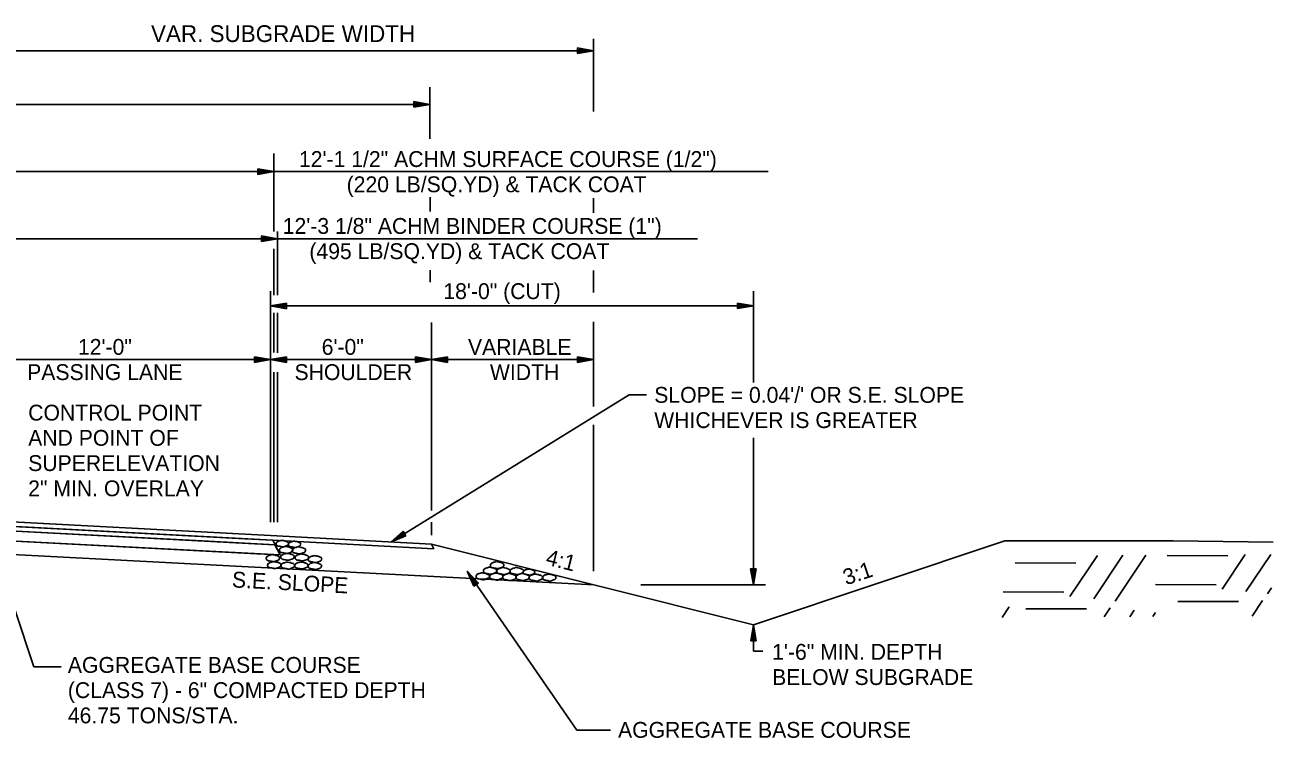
# Model space of a CAD drawing. Extents: x 1398183 to 1398373, y 1967240 to 1968889.
# Drawn here: x 1398257.9 to 1398304.42, y 1968551.85 to 1968578.41 of the extents above; entities that cross this region are included whole.
import ezdxf

# ---------------------------------------------------------------- set-up
doc = ezdxf.new("R2010")
doc.units = 0
for name, color, linetype in [('1', 7, 'Continuous'), ('10', 7, 'Continuous'), ('19', 7, 'Continuous'), ('42', 7, 'Continuous'), ('9', 7, 'Continuous'), ('Default', 7, 'Continuous'), ('Level 1', 7, 'Continuous')]:
    doc.layers.add(name, color=color, linetype=linetype)

# ---------------------------------------------------------------- blocks, each defined once
blk = doc.blocks.new('ROCKS')
at = {"layer": '1'}
blk.add_spline([(0.013, 0.06), (0.053, 0.053), (0.107, 0.033), (0.133, 0.013), (0.133, -0.007), (0.12, -0.033), (0.107, -0.04), (0.073, -0.053), (0.033, -0.067), (0.013, -0.067), (-0.02, -0.06), (-0.06, -0.053), (-0.087, -0.047), (-0.113, -0.02), (-0.113, -0.007), (-0.107, 0.02), (-0.087, 0.033), (-0.067, 0.047), (-0.033, 0.053), (-0.02, 0.06), (0.013, 0.06)], degree=3, dxfattribs=at)

msp = doc.modelspace()

# ---------------------------------------------------------------- linework, layer by layer
at = {"layer": '19'}
for p, q in [((1398279.092, 1968575.187), (1398279.092, 1968577.893)), ((1398255.052, 1968577.446), (1398279.092, 1968577.446)), ((1398278.492, 1968577.551), (1398278.492, 1968577.341)), ((1398279.092, 1968577.446), (1398278.492, 1968577.551)), ((1398278.932, 1968577.461), (1398278.492, 1968577.496)), ((1398278.492, 1968577.341), (1398279.092, 1968577.446)), ((1398278.492, 1968577.391), (1398278.932, 1968577.431)), ((1398272.994, 1968574.171), (1398272.994, 1968576.094)), ((1398272.994, 1968575.446), (1398220.994, 1968575.446)), ((1398272.394, 1968575.551), (1398272.394, 1968575.341)), ((1398272.994, 1968575.446), (1398272.394, 1968575.551)), ((1398272.834, 1968575.461), (1398272.394, 1968575.496)), ((1398272.394, 1968575.341), (1398272.994, 1968575.446)), ((1398272.394, 1968575.391), (1398272.834, 1968575.431)), ((1398267.175, 1968570.713), (1398267.175, 1968573.616)), ((1398255.052, 1968572.946), (1398285.602, 1968572.946)), ((1398266.574, 1968573.051), (1398266.574, 1968572.841)), ((1398267.174, 1968572.946), (1398266.574, 1968573.051)), ((1398267.014, 1968572.961), (1398266.574, 1968572.996)), ((1398266.574, 1968572.841), (1398267.174, 1968572.946)), ((1398266.574, 1968572.891), (1398267.014, 1968572.931)), ((1398273, 1968571.456), (1398273, 1968571.992)), ((1398279.092, 1968571.414), (1398279.092, 1968571.951)), ((1398220.994, 1968570.446), (1398282.96, 1968570.446)), ((1398266.712, 1968570.551), (1398266.712, 1968570.341)), ((1398267.312, 1968570.446), (1398266.712, 1968570.551)), ((1398267.152, 1968570.461), (1398266.712, 1968570.496)), ((1398266.712, 1968570.341), (1398267.312, 1968570.446)), ((1398266.712, 1968570.391), (1398267.152, 1968570.431)), ((1398267.312, 1968568.343), (1398267.312, 1968570.71)), ((1398267.175, 1968568.343), (1398267.175, 1968570.069)), ((1398273, 1968568.833), (1398273, 1968569.274)), ((1398279.092, 1968568.442), (1398279.092, 1968569.257)), ((1398267.052, 1968559.886), (1398267.052, 1968568.492)), ((1398285.051, 1968565.091), (1398285.051, 1968568.492)), ((1398267.652, 1968568.05), (1398267.052, 1968567.946)), ((1398267.652, 1968567.995), (1398267.212, 1968567.961)), ((1398267.652, 1968567.84), (1398267.652, 1968568.05)), ((1398284.452, 1968568.051), (1398284.452, 1968567.841)), ((1398285.052, 1968567.946), (1398284.452, 1968568.051)), ((1398284.892, 1968567.961), (1398284.452, 1968567.996)), ((1398285.052, 1968567.946), (1398267.052, 1968567.946)), ((1398267.052, 1968567.946), (1398267.652, 1968567.84)), ((1398267.175, 1968566.203), (1398267.175, 1968567.691)), ((1398267.212, 1968567.931), (1398267.652, 1968567.89)), ((1398267.312, 1968566.201), (1398267.312, 1968567.689)), ((1398284.452, 1968567.841), (1398285.052, 1968567.946)), ((1398284.452, 1968567.891), (1398284.892, 1968567.931)), ((1398273.052, 1968560.328), (1398273.052, 1968567.328)), ((1398279.091, 1968564.2), (1398279.091, 1968567.355)), ((1398255.052, 1968565.946), (1398267.052, 1968565.946)), ((1398266.452, 1968566.051), (1398266.452, 1968565.841)), ((1398267.052, 1968565.946), (1398266.452, 1968566.051)), ((1398266.892, 1968565.961), (1398266.452, 1968565.996)), ((1398266.452, 1968565.841), (1398267.052, 1968565.946)), ((1398266.452, 1968565.891), (1398266.892, 1968565.931)), ((1398267.652, 1968566.05), (1398267.052, 1968565.946)), ((1398267.052, 1968565.946), (1398273.052, 1968565.946)), ((1398267.052, 1968565.946), (1398267.652, 1968565.84)), ((1398267.652, 1968565.995), (1398267.212, 1968565.961)), ((1398267.212, 1968565.931), (1398267.652, 1968565.89)), ((1398267.652, 1968565.84), (1398267.652, 1968566.05)), ((1398272.452, 1968566.051), (1398272.452, 1968565.841)), ((1398273.052, 1968565.946), (1398272.452, 1968566.051)), ((1398272.892, 1968565.961), (1398272.452, 1968565.996)), ((1398272.452, 1968565.841), (1398273.052, 1968565.946)), ((1398272.452, 1968565.891), (1398272.892, 1968565.931)), ((1398273.652, 1968566.05), (1398273.052, 1968565.945)), ((1398273.052, 1968565.945), (1398279.091, 1968565.945)), ((1398273.052, 1968565.945), (1398273.652, 1968565.84)), ((1398273.652, 1968565.995), (1398273.212, 1968565.96)), ((1398273.212, 1968565.93), (1398273.652, 1968565.89)), ((1398273.652, 1968565.84), (1398273.652, 1968566.05)), ((1398278.491, 1968566.05), (1398278.491, 1968565.84)), ((1398279.091, 1968565.945), (1398278.491, 1968566.05)), ((1398278.931, 1968565.96), (1398278.491, 1968565.995)), ((1398278.491, 1968565.84), (1398279.091, 1968565.945)), ((1398278.491, 1968565.89), (1398278.931, 1968565.93)), ((1398267.175, 1968559.886), (1398267.175, 1968565.472)), ((1398267.312, 1968559.886), (1398267.312, 1968565.469)), ((1398280.42, 1968564.629), (1398271.536, 1968559.148)), ((1398281.067, 1968564.629), (1398280.42, 1968564.629)), ((1398279.091, 1968558.061), (1398279.091, 1968563.516)), ((1398285.051, 1968557.555), (1398285.051, 1968563.026)), ((1398255.052, 1968559.689), (1398267.222, 1968559.046)), ((1398266.472, 1968559.085), (1398255.511, 1968559.661)), ((1398273.052, 1968559.399), (1398273.052, 1968559.889)), ((1398267.411, 1968558.667), (1398255.052, 1968559.314)), ((1398267.137, 1968559.216), (1398267.222, 1968559.046)), ((1398271.536, 1968559.148), (1398271.992, 1968559.552)), ((1398272.1, 1968559.374), (1398271.536, 1968559.148)), ((1398271.665, 1968559.242), (1398272.017, 1968559.505)), ((1398272.074, 1968559.416), (1398271.68, 1968559.218)), ((1398271.992, 1968559.552), (1398272.1, 1968559.374)), ((1398285.051, 1968556.07), (1398294.413, 1968559.191)), ((1398258.23, 1968554.496), (1398256.72, 1968559.029)), ((1398267.215, 1968559.047), (1398266.472, 1968559.085)), ((1398266.538, 1968558.715), (1398267.411, 1968558.667)), ((1398267.411, 1968558.667), (1398267.215, 1968559.047)), ((1398267.222, 1968559.046), (1398267.411, 1968558.667)), ((1398273.052, 1968559.068), (1398285.052, 1968556.068)), ((1398273.052, 1968559.068), (1398273.137, 1968558.898)), ((1398278.468, 1968552.142), (1398274.381, 1968558.058)), ((1398274.633, 1968557.505), (1398274.381, 1968558.058)), ((1398274.381, 1968558.058), (1398274.806, 1968557.622)), ((1398274.674, 1968557.534), (1398274.457, 1968557.917)), ((1398274.48, 1968557.933), (1398274.761, 1968557.595)), ((1398285.156, 1968558.155), (1398284.946, 1968558.155)), ((1398284.946, 1968558.155), (1398285.051, 1968557.555)), ((1398284.996, 1968558.155), (1398285.036, 1968557.715)), ((1398285.051, 1968557.555), (1398285.156, 1968558.155)), ((1398285.066, 1968557.715), (1398285.101, 1968558.155)), ((1398274.806, 1968557.622), (1398274.633, 1968557.505)), ((1398285.052, 1968556.068), (1398284.947, 1968555.468)), ((1398285.037, 1968555.908), (1398285.002, 1968555.468)), ((1398285.157, 1968555.468), (1398285.052, 1968556.068)), ((1398285.107, 1968555.468), (1398285.067, 1968555.908)), ((1398284.947, 1968555.468), (1398285.157, 1968555.468)), ((1398259.243, 1968554.496), (1398258.23, 1968554.496)), ((1398279.72, 1968552.142), (1398278.468, 1968552.142))]:
    msp.add_line(p, q, dxfattribs=at)
for points in [[(1398220.967, 1968561.654), (1398230.818, 1968561.138), (1398243.052, 1968560.491), (1398267.137, 1968559.216), (1398273.137, 1968558.898), (1398273.052, 1968559.068), (1398267.052, 1968559.386), (1398243.052, 1968560.658), (1398231.052, 1968561.294), (1398221.052, 1968561.824)], [(1398255.053, 1968559.856), (1398255.052, 1968559.689), (1398255.876, 1968559.646), (1398264.734, 1968559.177), (1398267.222, 1968559.046), (1398267.137, 1968559.216), (1398266.088, 1968559.271), (1398255.817, 1968559.815)]]:
    msp.add_lwpolyline(points, close=True, dxfattribs=at)
for points in [[(1398220.967, 1968561.654), (1398243.052, 1968560.491), (1398267.137, 1968559.216), (1398273.137, 1968558.898)], [(1398221.052, 1968561.824), (1398231.052, 1968561.294), (1398243.052, 1968560.658), (1398255.052, 1968560.022), (1398267.052, 1968559.386), (1398273.052, 1968559.068)], [(1398255.046, 1968559.31), (1398255.626, 1968559.279), (1398266.538, 1968558.715)], [(1398255.052, 1968558.814), (1398267.411, 1968558.167), (1398279.105, 1968557.555)]]:
    msp.add_lwpolyline(points, dxfattribs=at)
at = {"layer": '42'}
msp.add_lwpolyline([(1398294.413, 1968559.191), (1398300.699, 1968559.191), (1398304.415, 1968559.14)], dxfattribs=at)
at = {"layer": '9'}
for p, q in [((1398297.868, 1968558.653), (1398296.845, 1968557.119)), ((1398298.82, 1968558.658), (1398297.736, 1968557.031)), ((1398299.68, 1968558.663), (1398298.533, 1968556.943)), ((1398303.378, 1968558.684), (1398302.517, 1968557.391)), ((1398304.331, 1968558.689), (1398303.407, 1968557.304)), ((1398297.061, 1968558.363), (1398294.799, 1968558.368)), ((1398302.733, 1968558.635), (1398300.471, 1968558.641)), ((1398296.622, 1968557.284), (1398294.36, 1968557.29)), ((1398302.294, 1968557.557), (1398300.032, 1968557.563)), ((1398304.359, 1968557.446), (1398304.205, 1968557.215)), ((1398303.132, 1968556.931), (1398300.87, 1968556.937)), ((1398304.021, 1968556.973), (1398303.633, 1968556.391)), ((1398294.585, 1968556.735), (1398294.321, 1968556.339)), ((1398297.46, 1968556.658), (1398295.198, 1968556.664)), ((1398298.349, 1968556.7), (1398298.122, 1968556.36)), ((1398299.24, 1968556.613), (1398299.075, 1968556.365)), ((1398300.038, 1968556.524), (1398299.935, 1968556.37))]:
    msp.add_line(p, q, dxfattribs=at)
at = {"layer": 'Default'}
msp.add_line((1398285.501, 1968557.555), (1398280.851, 1968557.555), dxfattribs=at)
msp.add_lwpolyline([(1398285.052, 1968556.068), (1398285.052, 1968555.089), (1398285.394, 1968555.089)], dxfattribs=at)

# ---------------------------------------------------------------- block references
at = {"layer": 'Level 1'}
for p, xscale, yscale, rotation in [((1398267.469, 1968559.094), 1.8771740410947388, 1.8771740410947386, -0.173618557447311), ((1398267.926, 1968559.069), 1.849824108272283, 1.8498241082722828, -0.17361855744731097), ((1398267.12, 1968558.553), 2.011654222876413, 2.0116542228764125, -0.17361855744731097), ((1398267.612, 1968558.859), 2.011654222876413, 2.0116542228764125, -0.17361855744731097), ((1398267.666, 1968558.604), 2.011654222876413, 2.0116542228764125, -0.17361855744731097), ((1398268.089, 1968558.844), 2.011654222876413, 2.0116542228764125, -0.17361855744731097), ((1398268.198, 1968558.581), 2.011654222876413, 2.0116542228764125, -0.17361855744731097), ((1398267.171, 1968558.296), 2.011654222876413, 2.0116542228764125, -0.17361855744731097), ((1398267.675, 1968558.278), 2.011654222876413, 2.0116542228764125, -0.17361855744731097), ((1398268.18, 1968558.281), 2.011654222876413, 2.0116542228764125, -0.17361855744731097), ((1398268.684, 1968558.262), 2.011654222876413, 2.0116542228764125, -0.17361855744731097), ((1398268.687, 1968558.52), 2.011654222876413, 2.0116542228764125, -0.17361855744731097), ((1398275.21, 1968558.086), 2.011654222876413, 2.0116542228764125, -0.17361855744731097), ((1398275.479, 1968558.294), 2.011654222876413, 2.0116542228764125, -0.17361855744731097), ((1398275.71, 1968558.074), 2.011654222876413, 2.0116542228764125, -0.17361855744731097), ((1398276.206, 1968558.074), 2.011654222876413, 2.0116542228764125, -0.17361855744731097), ((1398274.94, 1968557.879), 2.011654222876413, 2.0116542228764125, -0.17361855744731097), ((1398275.444, 1968557.869), 2.011654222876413, 2.0116542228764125, -0.17361855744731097), ((1398275.444, 1968557.869), 2.011654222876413, 2.0116542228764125, -0.17361855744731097), ((1398275.936, 1968557.85), 2.011654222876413, 2.0116542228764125, -0.17361855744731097), ((1398275.936, 1968557.85), 2.011654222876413, 2.0116542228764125, -0.17361855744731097), ((1398276.426, 1968557.85), 2.011654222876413, 2.0116542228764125, -0.17361855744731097), ((1398276.426, 1968557.85), 2.011654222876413, 2.0116542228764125, -0.17361855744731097), ((1398276.668, 1968558.035), 1.7335100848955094, 1.7335100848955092, -0.173618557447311), ((1398276.92, 1968557.831), 2.011654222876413, 2.0116542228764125, -0.17361855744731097), ((1398276.92, 1968557.831), 2.011654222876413, 2.0116542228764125, -0.17361855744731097), ((1398277.422, 1968557.831), 2.011654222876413, 2.0116542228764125, -0.17361855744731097), ((1398277.422, 1968557.831), 2.011654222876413, 2.0116542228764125, -0.17361855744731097)]:
    msp.add_blockref('ROCKS', p, dxfattribs=dict(at, xscale=xscale, yscale=yscale, rotation=rotation))

# ---------------------------------------------------------------- texts
at = {"layer": '10'}
for s, height, p in [('18\'-0" (CUT)', 0.59001, (1398273.492, 1968568.197)), ('12\'-0"', 0.59, (1398259.874, 1968566.121)), ('6\'-0"', 0.59, (1398268.958, 1968566.121)), ('VARIABLE', 0.59, (1398274.41, 1968566.12)), ('PASSING LANE', 0.59001, (1398257.981, 1968565.181)), ('SHOULDER', 0.59, (1398267.945, 1968565.181)), ('WIDTH', 0.59, (1398275.228, 1968565.18)), ('CONTROL POINT', 0.59001, (1398258.019, 1968563.673)), ('AND POINT OF ', 0.59001, (1398258.019, 1968562.733)), ('SUPERELEVATION', 0.59001, (1398258.019, 1968561.793)), ('2" MIN. OVERLAY', 0.59001, (1398258.019, 1968560.853))]:
    msp.add_text(s, height=height, dxfattribs=at).set_placement(p)
for s, height, rotation, p in [('4:1', 0.59, 345.9638, (1398277.276, 1968558.316)), ('3:1', 0.59, 18.4349, (1398288.504, 1968557.532)), ('1\'-6" MIN. DEPTH', 0.59001, 360, (1398285.746, 1968554.764)), ('BELOW SUBGRADE', 0.59001, 360, (1398285.746, 1968553.824))]:
    msp.add_text(s, height=height, rotation=rotation, dxfattribs=at).set_placement(p)
at = {"layer": '19'}
for s, height, p in [('VAR. SUBGRADE WIDTH', 0.625, (1398262.597, 1968577.771)), ("SLOPE = 0.04'/' OR S.E. SLOPE", 0.59001, (1398281.352, 1968564.334)), ('WHICHEVER IS GREATER', 0.59001, (1398281.352, 1968563.394))]:
    msp.add_text(s, height=height, dxfattribs=at).set_placement(p)
for s, height, rotation, p in [('S.E. SLOPE', 0.59, 356.9662, (1398265.602, 1968557.463)), ('AGGREGATE BASE COURSE', 0.59001, 360, (1398259.497, 1968554.277)), ('(CLASS 7) - 6" COMPACTED DEPTH', 0.59001, 360, (1398259.497, 1968553.337)), ('46.75 TONS/STA.', 0.59001, 360, (1398259.497, 1968552.397)), ('AGGREGATE BASE COURSE', 0.59001, 360, (1398280.003, 1968551.858))]:
    msp.add_text(s, height=height, rotation=rotation, dxfattribs=at).set_placement(p)
at = {"layer": '42'}
for s, p in [('12\'-1 1/2" ACHM SURFACE COURSE (1/2")', (1398268.111, 1968573.117)), ('(220 LB/SQ.YD) & TACK COAT', (1398269.888, 1968572.177)), ('12\'-3 1/8" ACHM BINDER COURSE (1")', (1398267.506, 1968570.626)), ('(495 LB/SQ.YD) & TACK COAT', (1398268.498, 1968569.686))]:
    msp.add_text(s, height=0.59001, rotation=360, dxfattribs=at).set_placement(p)

doc.saveas('drawing.dxf')
